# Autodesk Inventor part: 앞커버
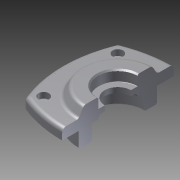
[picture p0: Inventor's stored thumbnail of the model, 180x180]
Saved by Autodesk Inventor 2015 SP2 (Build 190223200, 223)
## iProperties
Created: 2013-02
Part Number: 앞커버
Document SubType Name: Modeling
Designer: 한국산업디자인학원[gmhk.co.kr]
Density: 1 g/cm^3
Material: 일반
Appearance: 기본값
Author: 한국산업디자인학원[gmhk.co.kr]
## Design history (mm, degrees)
sketch "스케치1"
  geometry: C1 r 30 at (0, 0) reference; A1 r 91.05 centre (0, -48.55) between (34.185, 35.839) and (-34.185, 35.839) reference; A2 r 91.05 centre (48.55, 0) between (-35.839, 34.185) and (-35.839, -34.185) reference; A3 r 3 centre (-33.058, 33.058) between (-34.185, 35.839) and (-35.839, 34.185) reference; A4 r 3 centre (33.058, 33.058) between (35.839, 34.185) and (34.185, 35.839) reference; A5 r 91.05 centre (-48.55, 0) between (35.839, -34.185) and (35.839, 34.185) reference; A6 r 3 centre (33.058, -33.058) between (34.185, -35.839) and (35.839, -34.185) reference; A7 r 91.05 centre (0, 48.55) between (-34.185, -35.839) and (34.185, -35.839) reference; A8 r 3 centre (-33.058, -33.058) between (-35.839, -34.185) and (-34.185, -35.839) reference; 1 further point
  node "참조1"
  node "참조2"
  node "참조3"
  node "참조4"
  node "참조5"
  node "참조6"
  node "참조7"
  node "참조8"
  node "참조9"
extrude "돌출1" new body sketch "스케치1" distance "d0" = 8; taper "d1" = 0 deg
sketch "스케치2"
  geometry: C1 r 30 at (0, 0); 1 further point
  constraints: 1 centre point, 1 coincident
  dimensions: "d2" = 60 diameter of C1
extrude "돌출2" join sketch "스케치2" distance "d3" = 7; taper "d4" = -30 deg
hole "구멍1" diameter "d7" = 20; stored, may be unused: countersink angle "d11" = 90 deg, drill point angle "d13" = 118 deg; dims "d5" = 10, "d6" = 10, "d8" = 6, "d9" = 30, "d10" = 8, "d12" = 20
sketch "스케치3"
  geometry: C1 r 1.621 at (28.284, 28.284) reference; C2 r 1.621 at (-28.284, 28.284) reference; C3 r 1.621 at (-28.284, -28.284) reference; C4 r 1.621 at (28.284, -28.284) reference; 1 further point
hole "구멍2" sketch "스케치3" at (28.284, 28.284), (28.284, -28.284), (-28.284, -28.284), (-28.284, 28.284) diameter "d14" = 4.5; stored, may be unused: countersink angle "d18" = 90 deg, drill point angle "d20" = 118 deg; dims "d15" = 6, "d16" = 8, "d17" = 4.4, "d19" = 20
extrude "돌출3" join sketch "스케치1" distance "d21" = 12; taper "d22" = 0 deg
hole "구멍3" diameter "d25" = 30; stored, may be unused: countersink angle "d29" = 90 deg, drill point angle "d31" = 0 deg; dims "d23" = 10, "d24" = 10, "d26" = 6, "d27" = 40, "d28" = 12, "d30" = 15
fillet "모깎기1" dims "d32" = 3, "d33" = 0.3
chamfer "모따기1" distance "d34" = 1; stored, may be unused: second distance "d35" = 2, angle "d36" = 45 deg
sketch "스케치4"
  geometry: L1 (0, 57.809)-(47.052, 57.809); L2 (47.052, 57.809)-(47.052, -44.739); L3 (47.052, -44.739)-(0, -44.739); L4 (0, -44.739)-(0, 57.809); 1 further point
  constraints: 8 end point, 2 parallel, 1 horizontal, 1 perpendicular
extrude "돌출4" cut sketch "스케치4" distance "d37" = 123; taper "d38" = 0 deg
node "솔리드1"
node "참조10"
node "참조11"
node "참조12"
node "참조13"
